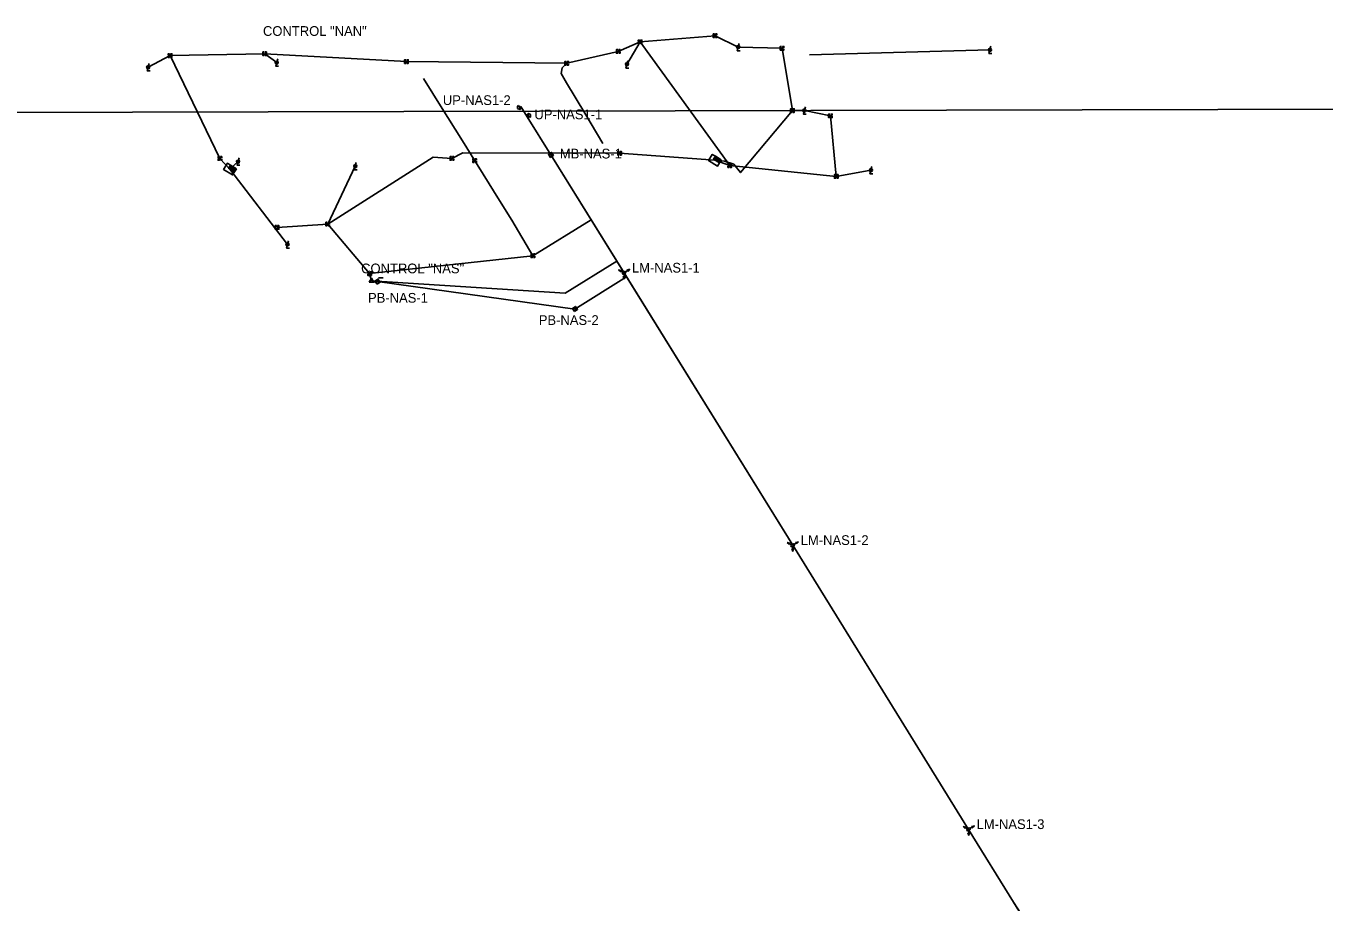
# Model space of a CAD drawing. Extents: x 1689971 to 1704302, y 703122 to 745602.
# Drawn here: x 1697142 to 1698211, y 718629 to 719350 of the extents above; entities that cross this region are included whole.
import ezdxf

# ---------------------------------------------------------------- set-up
doc = ezdxf.new("R2010")
doc.units = 0
for name, color, linetype in [('_CIVIL_CONSTRUCTION', 7, 'Continuous'), ('PF_X_Ground_Line', 7, 'Continuous'), ('RD_X_Cells', 7, 'Continuous'), ('RD_X_Concrete_Barrier', 7, 'Continuous'), ('SC_ProfileRun2', 7, 'Continuous'), ('SC_Scratch2', 7, 'Continuous'), ('SC_Scratch3', 7, 'Continuous'), ('SC_Scratch4', 7, 'Continuous'), ('SV_X_Control_Cells_Found', 7, 'Continuous'), ('SV_X_Mon_Cells_Found', 7, 'Continuous'), ('SV_X_Random_Point', 7, 'Continuous'), ('SV_X_Shot_Marker', 7, 'Continuous')]:
    doc.layers.add(name, color=color, linetype=linetype)

msp = doc.modelspace()

# ---------------------------------------------------------------- linework, layer by layer
at = {"layer": '_CIVIL_CONSTRUCTION'}
for p, q in [((1697630.1, 719329.4), (1697648.1, 719337.3)), ((1697648.1, 719337.3), (1697637.3, 719318.7)), ((1697709.9, 719342.3), (1697648.1, 719337.3)), ((1697722, 719235.4), (1697648.1, 719337.3)), ((1697709.9, 719342.3), (1697728.9, 719333)), ((1697243.1, 719316.4), (1697261.1, 719326)), ((1697261.1, 719326), (1697339, 719327.5)), ((1697302.1, 719241.3), (1697261.1, 719326)), ((1697455.7, 719321.1), (1697339, 719327.5)), ((1697339, 719327.5), (1697348.9, 719320.2)), ((1697630.1, 719329.4), (1697587.7, 719319.7)), ((1697765, 719332), (1697728.9, 719333)), ((1697773.6, 719280.7), (1697765, 719332)), ((1697936.2, 719330.6), (1697787.6, 719326.5)), ((1697587.7, 719319.7), (1697455.7, 719321.1)), ((1697773.6, 719280.7), (1697783.4, 719280.8)), ((1697773.6, 719280.7), (1697783.4, 719280.8)), ((1697783.4, 719280.8), (1697804.8, 719276.4)), ((1697809.6, 719226.5), (1697804.8, 719276.4)), ((1697302.1, 719241.3), (1697310.4, 719232.6)), ((1697317.1, 719238.7), (1697310.4, 719232.6)), ((1697631.3, 719245.6), (1697709.8, 719239.9)), ((1697709.8, 719239.9), (1697722, 719235.4)), ((1697310.4, 719232.6), (1697357.8, 719170.5)), ((1697390.9, 719187.3), (1697413.6, 719234.9)), ((1697809.6, 719226.5), (1697722, 719235.4)), ((1697809.6, 719226.5), (1697838.2, 719231.7)), ((1697349.2, 719184.5), (1697390.9, 719187.3)), ((1697559.9, 719161.2), (1697607.8, 719190.9)), ((1697559.9, 719161.2), (1697425.4, 719146.5))]:
    msp.add_line(p, q, dxfattribs=at)
for points in [[(1697587.6, 719303.5), (1697583.1, 719311.1), (1697584, 719315.9), (1697587.7, 719319.7)], [(1697500.6, 719257.9), (1697485.2, 719282.5), (1697469.8, 719307.1)], [(1697617.4, 719253.7), (1697602.5, 719278.6), (1697587.6, 719303.5)], [(1697709.8, 719239.9), (1697717.5, 719239.2), (1697725.3, 719236.5), (1697730.9, 719229.7), (1697773.6, 719280.7)], [(1697559.9, 719161.2), (1697542.4, 719190.6), (1697532.4, 719206.7), (1697500.6, 719257.9)], [(1697390.9, 719187.3), (1697477.7, 719242.5), (1697493.2, 719241.4)], [(1697493.2, 719241.4), (1697502.2, 719245.9), (1697631.3, 719245.6)], [(1697426.9, 719140.6), (1697425.4, 719146.5), (1697390.9, 719187.3)]]:
    msp.add_lwpolyline(points, dxfattribs=at)
at = {"layer": 'PF_X_Ground_Line'}
msp.add_lwpolyline([(1697425, 719139.4), (1697428.9, 719139.4), (1697426.9, 719142.9)], close=True, dxfattribs=at)
at = {"layer": 'RD_X_Cells'}
for p, q in [((1697634.9, 719147.2), (1697574.7, 719244.3)), ((1697637, 719143.8), (1697594.5, 719117.4)), ((1697773.8, 718922.9), (1697634.9, 719147.2)), ((1697426.9, 719140.6), (1697431.9, 719140)), ((1697918.6, 718689.1), (1697773.8, 718922.9)), ((1697955.6, 718629.3), (1697918.6, 718689.1))]:
    msp.add_line(p, q, dxfattribs=at)
msp.add_arc((1700391, 720137.9), 2864.8, 211.776, 215.5389, dxfattribs=at)
at = {"layer": 'RD_X_Concrete_Barrier'}
for p, q in [((1697550, 719284.2), (1697548.3, 719283.2)), ((1697555.2, 719275.7), (1697550, 719284.2)), ((1697555.2, 719275.7), (1697556.9, 719276.8)), ((1697574.7, 719244.3), (1697555.2, 719275.7)), ((1697629, 719156.7), (1697574.7, 719244.3)), ((1697773.8, 718922.9), (1697629, 719156.7)), ((1697431.9, 719140), (1697594.5, 719117.4)), ((1697918.6, 718689.1), (1697773.8, 718922.9)), ((1697955.6, 718629.3), (1697918.6, 718689.1))]:
    msp.add_line(p, q, dxfattribs=at)
msp.add_arc((1700391, 720137.9), 2864.8, 211.776, 215.3689, dxfattribs=at)
at = {"layer": 'SC_ProfileRun2'}
for p, q in [((1697711.8, 719241.8), (1697708.9, 719240.7)), ((1697710.1, 719242.8), (1697710.5, 719239.7)), ((1697714.8, 719240.1), (1697710.4, 719239.6)), ((1697711.8, 719241.9), (1697713.4, 719237.8)), ((1697312.4, 719234.5), (1697309.6, 719233.5)), ((1697310.8, 719235.5), (1697311.2, 719232.5)), ((1697315.5, 719232.8), (1697311.1, 719232.4)), ((1697312.5, 719234.6), (1697314.1, 719230.5))]:
    msp.add_line(p, q, dxfattribs=at)
for points in [[(1697315.7, 719232.9), (1697314.2, 719230.3), (1697312.6, 719227.7), (1697305.1, 719232.3), (1697308.3, 719237.4), (1697310.8, 719235.9)], [(1697715, 719240.2), (1697713.5, 719237.6), (1697711.9, 719235), (1697704.5, 719239.6), (1697707.6, 719244.7), (1697710.1, 719243.1)], [(1697708.9, 719240.7), (1697710.1, 719242.8), (1697711.8, 719241.8), (1697710.5, 719239.7)], [(1697713.4, 719237.8), (1697710.4, 719239.6), (1697711.8, 719241.9), (1697714.8, 719240.1)], [(1697309.6, 719233.5), (1697310.8, 719235.5), (1697312.4, 719234.5), (1697311.2, 719232.5)], [(1697314.1, 719230.5), (1697311.1, 719232.4), (1697312.5, 719234.6), (1697315.5, 719232.8)]]:
    msp.add_lwpolyline(points, close=True, dxfattribs=at)
for points in [[(1697710.1, 719243.1), (1697708.6, 719240.6), (1697713.5, 719237.6)], [(1697310.8, 719235.9), (1697309.3, 719233.3), (1697314.2, 719230.3)]]:
    msp.add_lwpolyline(points, dxfattribs=at)
at = {"layer": 'SC_Scratch2'}
for p in [(1697548.3, 719283.2), (1697555.2, 719275.7)]:
    msp.add_line(p, (1697550, 719284.2), dxfattribs=at)
at = {"layer": 'SC_Scratch3'}
for points in [[(1697729.7, 719336), (1697728.2, 719330), (1697730.5, 719330)], [(1697937, 719333.6), (1697935.4, 719327.6), (1697937.8, 719327.6)], [(1697349.7, 719323.2), (1697348.1, 719317.2), (1697350.5, 719317.2)], [(1697243.9, 719319.4), (1697242.3, 719313.4), (1697244.7, 719313.4)], [(1697638.1, 719321.7), (1697636.5, 719315.7), (1697638.9, 719315.7)], [(1697784.2, 719283.8), (1697782.6, 719277.8), (1697785, 719277.8)], [(1697317.9, 719241.7), (1697316.3, 719235.7), (1697318.6, 719235.7)], [(1697414.4, 719237.9), (1697412.8, 719231.9), (1697415.2, 719231.9)], [(1697839, 719234.7), (1697837.4, 719228.7), (1697839.8, 719228.7)], [(1697358.6, 719173.5), (1697357, 719167.6), (1697359.4, 719167.6)]]:
    msp.add_lwpolyline(points, dxfattribs=at)
for centre in [(1697728.9, 719333.1), (1697936.2, 719330.7), (1697243.1, 719316.4), (1697348.9, 719320.2), (1697637.3, 719318.8), (1697783.4, 719280.8), (1697317.1, 719238.7), (1697413.6, 719235), (1697838.2, 719231.7), (1697357.8, 719170.6)]:
    msp.add_circle(centre, 1.3, dxfattribs=at)
at = {"layer": 'SC_Scratch4'}
for p, q in [((1697648.1, 719337.3), (1697648.1, 719337.3)), ((1697709.9, 719342.3), (1697709.9, 719342.3)), ((1697261.1, 719326), (1697261.1, 719326)), ((1697339, 719327.5), (1697339, 719327.5)), ((1697630.1, 719329.4), (1697630.1, 719329.4)), ((1697765, 719332), (1697765, 719332)), ((1697455.7, 719321.1), (1697455.7, 719321.1)), ((1697587.7, 719319.7), (1697587.7, 719319.7)), ((1697773.6, 719280.7), (1697773.6, 719280.7)), ((1697804.8, 719276.4), (1697804.8, 719276.4)), ((1697302.1, 719241.3), (1697302.1, 719241.3)), ((1697493.2, 719241.4), (1697493.2, 719241.4)), ((1697511.9, 719239.6), (1697511.9, 719239.6)), ((1697631.3, 719245.6), (1697631.3, 719245.6)), ((1697722, 719235.4), (1697722, 719235.4)), ((1697809.6, 719226.5), (1697809.6, 719226.5)), ((1697349.2, 719184.5), (1697349.2, 719184.5)), ((1697390.9, 719187.3), (1697390.9, 719187.3)), ((1697559.9, 719161.2), (1697559.9, 719161.2)), ((1697425.4, 719146.5), (1697425.4, 719146.5))]:
    msp.add_line(p, q, dxfattribs=at)
for points in [[(1697647.7, 719338.8), (1697646.6, 719338.8), (1697646.6, 719337.7)], [(1697646.6, 719336.9), (1697646.6, 719335.8), (1697647.7, 719335.8)], [(1697647, 719338.3), (1697647, 719336.3), (1697648.1, 719336.3)], [(1697648, 719338.3), (1697649.3, 719338.3)], [(1697649.6, 719337.7), (1697649.6, 719338.8), (1697648.5, 719338.8)], [(1697648.5, 719335.8), (1697649.6, 719335.8), (1697649.6, 719336.9)], [(1697648.7, 719338.3), (1697648.7, 719336.3)], [(1697709.5, 719343.8), (1697708.4, 719343.8), (1697708.4, 719342.7)], [(1697708.4, 719341.9), (1697708.4, 719340.8), (1697709.5, 719340.8)], [(1697708.8, 719343.3), (1697708.8, 719341.3), (1697709.9, 719341.3)], [(1697709.8, 719343.3), (1697711.1, 719343.3)], [(1697711.4, 719342.7), (1697711.4, 719343.8), (1697710.3, 719343.8)], [(1697710.3, 719340.8), (1697711.4, 719340.8), (1697711.4, 719341.9)], [(1697710.5, 719343.3), (1697710.5, 719341.3)], [(1697260.7, 719327.5), (1697259.6, 719327.5), (1697259.6, 719326.4)], [(1697259.6, 719325.6), (1697259.6, 719324.5), (1697260.7, 719324.5)], [(1697260, 719327), (1697260, 719325), (1697261.1, 719325)], [(1697261, 719327), (1697262.3, 719327)], [(1697262.6, 719326.4), (1697262.6, 719327.5), (1697261.5, 719327.5)], [(1697261.5, 719324.5), (1697262.6, 719324.5), (1697262.6, 719325.6)], [(1697261.6, 719327), (1697261.6, 719325)], [(1697338.6, 719329), (1697337.5, 719329), (1697337.5, 719327.9)], [(1697337.5, 719327.1), (1697337.5, 719326), (1697338.6, 719326)], [(1697337.9, 719328.5), (1697337.9, 719326.5), (1697339, 719326.5)], [(1697339, 719328.5), (1697340.2, 719328.5)], [(1697340.5, 719327.9), (1697340.5, 719329), (1697339.4, 719329)], [(1697339.4, 719326), (1697340.5, 719326), (1697340.5, 719327.1)], [(1697339.6, 719328.5), (1697339.6, 719326.5)], [(1697629.7, 719330.9), (1697628.6, 719330.9), (1697628.6, 719329.8)], [(1697628.6, 719329), (1697628.6, 719327.9), (1697629.7, 719327.9)], [(1697629, 719330.4), (1697629, 719328.4), (1697630.1, 719328.4)], [(1697630, 719330.4), (1697631.3, 719330.4)], [(1697631.6, 719329.8), (1697631.6, 719330.9), (1697630.5, 719330.9)], [(1697630.5, 719327.9), (1697631.6, 719327.9), (1697631.6, 719329)], [(1697630.6, 719330.4), (1697630.6, 719328.4)], [(1697764.6, 719333.5), (1697763.5, 719333.5), (1697763.5, 719332.4)], [(1697763.5, 719331.6), (1697763.5, 719330.5), (1697764.6, 719330.5)], [(1697764, 719333), (1697764, 719331), (1697765, 719331)], [(1697765, 719333), (1697766.2, 719333)], [(1697766.5, 719332.4), (1697766.5, 719333.5), (1697765.4, 719333.5)], [(1697765.4, 719330.5), (1697766.5, 719330.5), (1697766.5, 719331.6)], [(1697765.6, 719333), (1697765.6, 719331)], [(1697455.3, 719322.6), (1697454.2, 719322.6), (1697454.2, 719321.5)], [(1697454.2, 719320.7), (1697454.2, 719319.6), (1697455.3, 719319.6)], [(1697454.7, 719322.1), (1697454.7, 719320.1), (1697455.7, 719320.1)], [(1697455.7, 719322.1), (1697456.9, 719322.1)], [(1697457.2, 719321.5), (1697457.2, 719322.6), (1697456.1, 719322.6)], [(1697456.1, 719319.6), (1697457.2, 719319.6), (1697457.2, 719320.7)], [(1697456.3, 719322.1), (1697456.3, 719320.1)], [(1697587.3, 719321.2), (1697586.2, 719321.2), (1697586.2, 719320.1)], [(1697586.2, 719319.3), (1697586.2, 719318.2), (1697587.3, 719318.2)], [(1697586.6, 719320.7), (1697586.6, 719318.7), (1697587.7, 719318.7)], [(1697587.6, 719320.7), (1697588.9, 719320.7)], [(1697589.2, 719320.1), (1697589.2, 719321.2), (1697588.1, 719321.2)], [(1697588.1, 719318.2), (1697589.2, 719318.2), (1697589.2, 719319.3)], [(1697588.3, 719320.7), (1697588.3, 719318.7)], [(1697773.2, 719282.2), (1697772.1, 719282.2), (1697772.1, 719281.1)], [(1697772.1, 719280.3), (1697772.1, 719279.2), (1697773.2, 719279.2)], [(1697772.5, 719281.7), (1697772.5, 719279.7), (1697773.6, 719279.7)], [(1697773.6, 719281.7), (1697774.8, 719281.7)], [(1697775.1, 719281.1), (1697775.1, 719282.2), (1697774, 719282.2)], [(1697774, 719279.2), (1697775.1, 719279.2), (1697775.1, 719280.3)], [(1697774.2, 719281.7), (1697774.2, 719279.7)], [(1697804.4, 719277.9), (1697803.3, 719277.9), (1697803.3, 719276.8)], [(1697803.3, 719276), (1697803.3, 719274.9), (1697804.4, 719274.9)], [(1697803.7, 719277.4), (1697803.7, 719275.4), (1697804.8, 719275.4)], [(1697804.8, 719277.4), (1697806, 719277.4)], [(1697806.3, 719276.8), (1697806.3, 719277.9), (1697805.2, 719277.9)], [(1697805.2, 719274.9), (1697806.3, 719274.9), (1697806.3, 719276)], [(1697805.4, 719277.4), (1697805.4, 719275.4)], [(1697301.7, 719242.8), (1697300.6, 719242.8), (1697300.6, 719241.7)], [(1697300.6, 719240.9), (1697300.6, 719239.8), (1697301.7, 719239.8)], [(1697301.1, 719242.3), (1697301.1, 719240.3), (1697302.1, 719240.3)], [(1697302.1, 719242.3), (1697303.3, 719242.3)], [(1697303.6, 719241.7), (1697303.6, 719242.8), (1697302.5, 719242.8)], [(1697302.5, 719239.8), (1697303.6, 719239.8), (1697303.6, 719240.9)], [(1697302.7, 719242.3), (1697302.7, 719240.3)], [(1697492.8, 719242.9), (1697491.7, 719242.9), (1697491.7, 719241.8)], [(1697491.7, 719241), (1697491.7, 719239.9), (1697492.8, 719239.9)], [(1697492.1, 719242.4), (1697492.1, 719240.4), (1697493.2, 719240.4)], [(1697493.1, 719242.4), (1697494.4, 719242.4)], [(1697494.7, 719241.8), (1697494.7, 719242.9), (1697493.6, 719242.9)], [(1697493.6, 719239.9), (1697494.7, 719239.9), (1697494.7, 719241)], [(1697493.8, 719242.4), (1697493.8, 719240.4)], [(1697511.5, 719241.1), (1697510.4, 719241.1), (1697510.4, 719240)], [(1697510.4, 719239.2), (1697510.4, 719238.1), (1697511.5, 719238.1)], [(1697510.8, 719240.6), (1697510.8, 719238.6), (1697511.9, 719238.6)], [(1697511.9, 719240.6), (1697513.1, 719240.6)], [(1697513.4, 719240), (1697513.4, 719241.1), (1697512.3, 719241.1)], [(1697512.3, 719238.1), (1697513.4, 719238.1), (1697513.4, 719239.2)], [(1697512.5, 719240.6), (1697512.5, 719238.6)], [(1697630.9, 719247.1), (1697629.8, 719247.1), (1697629.8, 719246)], [(1697629.8, 719245.2), (1697629.8, 719244.1), (1697630.9, 719244.1)], [(1697630.2, 719246.6), (1697630.2, 719244.6), (1697631.3, 719244.6)], [(1697631.3, 719246.6), (1697632.5, 719246.6)], [(1697632.8, 719246), (1697632.8, 719247.1), (1697631.7, 719247.1)], [(1697631.7, 719244.1), (1697632.8, 719244.1), (1697632.8, 719245.2)], [(1697631.9, 719246.6), (1697631.9, 719244.6)], [(1697721.6, 719236.9), (1697720.5, 719236.9), (1697720.5, 719235.8)], [(1697720.5, 719235), (1697720.5, 719233.9), (1697721.6, 719233.9)], [(1697720.9, 719236.4), (1697720.9, 719234.4), (1697722, 719234.4)], [(1697722, 719236.4), (1697723.2, 719236.4)], [(1697723.5, 719235.8), (1697723.5, 719236.9), (1697722.4, 719236.9)], [(1697722.4, 719233.9), (1697723.5, 719233.9), (1697723.5, 719235)], [(1697722.6, 719236.4), (1697722.6, 719234.4)], [(1697809.2, 719228), (1697808.1, 719228), (1697808.1, 719226.9)], [(1697808.5, 719227.5), (1697808.5, 719225.5), (1697809.6, 719225.5)], [(1697809.5, 719227.5), (1697810.8, 719227.5)], [(1697811.1, 719226.9), (1697811.1, 719228), (1697810, 719228)], [(1697810.1, 719227.5), (1697810.1, 719225.5)], [(1697808.1, 719226.1), (1697808.1, 719225), (1697809.2, 719225)], [(1697810, 719225), (1697811.1, 719225), (1697811.1, 719226.1)], [(1697348.8, 719186), (1697347.7, 719186), (1697347.7, 719184.9)], [(1697347.7, 719184.1), (1697347.7, 719183), (1697348.8, 719183)], [(1697348.1, 719185.5), (1697348.1, 719183.5), (1697349.2, 719183.5)], [(1697349.1, 719185.5), (1697350.4, 719185.5)], [(1697350.7, 719184.9), (1697350.7, 719186), (1697349.6, 719186)], [(1697349.6, 719183), (1697350.7, 719183), (1697350.7, 719184.1)], [(1697349.8, 719185.5), (1697349.8, 719183.5)], [(1697390.5, 719188.8), (1697389.4, 719188.8), (1697389.4, 719187.7)], [(1697389.4, 719186.9), (1697389.4, 719185.8), (1697390.5, 719185.8)], [(1697389.8, 719188.3), (1697389.8, 719186.3), (1697390.9, 719186.3)], [(1697390.9, 719188.3), (1697392.1, 719188.3)], [(1697392.4, 719187.7), (1697392.4, 719188.8), (1697391.3, 719188.8)], [(1697391.3, 719185.8), (1697392.4, 719185.8), (1697392.4, 719186.9)], [(1697391.5, 719188.3), (1697391.5, 719186.3)], [(1697559.5, 719162.7), (1697558.4, 719162.7), (1697558.4, 719161.6)], [(1697561.4, 719161.6), (1697561.4, 719162.7), (1697560.3, 719162.7)], [(1697558.4, 719160.8), (1697558.4, 719159.7), (1697559.5, 719159.7)], [(1697558.8, 719162.2), (1697558.8, 719160.2), (1697559.9, 719160.2)], [(1697559.8, 719162.2), (1697561.1, 719162.2)], [(1697560.3, 719159.7), (1697561.4, 719159.7), (1697561.4, 719160.8)], [(1697560.5, 719162.2), (1697560.5, 719160.2)], [(1697425, 719148), (1697423.9, 719148), (1697423.9, 719146.9)], [(1697423.9, 719146.1), (1697423.9, 719145), (1697425, 719145)], [(1697424.3, 719147.5), (1697424.3, 719145.5), (1697425.4, 719145.5)], [(1697425.4, 719147.5), (1697426.6, 719147.5)], [(1697426.9, 719146.9), (1697426.9, 719148), (1697425.8, 719148)], [(1697425.8, 719145), (1697426.9, 719145), (1697426.9, 719146.1)], [(1697426, 719147.5), (1697426, 719145.5)]]:
    msp.add_lwpolyline(points, dxfattribs=at)
at = {"layer": 'SV_X_Control_Cells_Found'}
for p, q in [((1697632.8, 719149), (1697630.4, 719149.6)), ((1697630.4, 719149.6), (1697632.2, 719147.9)), ((1697633.9, 719147.7), (1697632.3, 719148.5)), ((1697634.3, 719144.5), (1697635, 719142.1)), ((1697634.9, 719146.1), (1697635, 719144.3)), ((1697635, 719142.1), (1697635.6, 719144.5)), ((1697636.2, 719148), (1697637.8, 719149)), ((1697639.6, 719150.1), (1697637.3, 719149.4)), ((1697637.9, 719148.3), (1697639.6, 719150.1)), ((1697771.7, 718924.8), (1697769.3, 718925.3)), ((1697769.3, 718925.3), (1697771.1, 718923.6)), ((1697772.8, 718923.4), (1697771.2, 718924.3)), ((1697773.2, 718920.2), (1697773.9, 718917.8)), ((1697773.8, 718921.8), (1697773.9, 718920)), ((1697773.9, 718917.8), (1697774.5, 718920.2)), ((1697775.1, 718923.8), (1697776.7, 718924.7)), ((1697778.6, 718925.9), (1697776.2, 718925.1)), ((1697776.8, 718924), (1697778.6, 718925.9)), ((1697916.5, 718691), (1697914.1, 718691.6)), ((1697914.1, 718691.6), (1697915.9, 718689.9)), ((1697917.6, 718689.7), (1697916.1, 718690.5)), ((1697918, 718686.4), (1697918.7, 718684.1)), ((1697918.6, 718688), (1697918.7, 718686.3)), ((1697918.7, 718684.1), (1697919.3, 718686.5)), ((1697920, 718690), (1697921.5, 718690.9)), ((1697923.4, 718692.1), (1697921, 718691.4)), ((1697921.7, 718690.3), (1697923.4, 718692.1))]:
    msp.add_line(p, q, dxfattribs=at)
for points in [[(1697548, 719284.9), (1697549.8, 719282.2), (1697549, 719281.7), (1697547.3, 719282.5), (1697547.2, 719284.4)], [(1697557.2, 719275), (1697555.4, 719277.7), (1697556.2, 719278.2), (1697557.9, 719277.4), (1697558, 719275.5)]]:
    msp.add_lwpolyline(points, close=True, dxfattribs=at)
for centre, start, end in [((1697633.3, 719148), 117.237, 186.3149), ((1697634.9, 719145.4), 237.237, 306.3149), ((1697636.8, 719148.4), 357.237, 66.3149), ((1697772.2, 718923.8), 117.0577, 186.1355), ((1697773.8, 718921.2), 237.0577, 306.1355), ((1697775.7, 718924.1), 357.0577, 66.1355), ((1697917.1, 718690), 116.9143, 185.9922), ((1697918.6, 718687.4), 236.9143, 305.9922), ((1697920.5, 718690.3), 356.9143, 65.9922)]:
    msp.add_arc(centre, 1.13, start, end, dxfattribs=at)
for centre, major_axis in [((1697634.9, 719147.2), (1.36, 0.84)), ((1697773.8, 718922.9), (1.36, 0.84)), ((1697918.6, 718689.1), (1.36, 0.83))]:
    msp.add_ellipse(centre, major_axis=major_axis, ratio=0.625, dxfattribs=at)
at = {"layer": 'SV_X_Mon_Cells_Found'}
msp.add_line((1697555.2, 719275.7), (1697556.9, 719276.8), dxfattribs=at)
at = {"layer": 'SV_X_Random_Point'}
for p, q in [((1698867.3, 719283.4), (1696073.6, 719276.6)), ((1697629, 719156.7), (1697586.5, 719130.4)), ((1697432.6, 719143.1), (1697436.6, 719143.1)), ((1697426.9, 719140.6), (1697586.5, 719130.4)), ((1697431.9, 719140), (1697426.9, 719140.6))]:
    msp.add_line(p, q, dxfattribs=at)
at = {"layer": 'SV_X_Shot_Marker'}
for p, q in [((1697574.7, 719244.3), (1697574.7, 719244.3)), ((1697431.9, 719140), (1697431.9, 719140)), ((1697594.5, 719117.4), (1697594.5, 719117.4))]:
    msp.add_line(p, q, dxfattribs=at)
for points in [[(1697574.2, 719242.2), (1697572.7, 719244.8), (1697575.2, 719246.3), (1697576.8, 719243.8)], [(1697431.5, 719137.9), (1697429.8, 719140.4), (1697432.3, 719142.1), (1697434, 719139.6)], [(1697594.1, 719115.4), (1697592.4, 719117.8), (1697594.9, 719119.5), (1697596.6, 719117)]]:
    msp.add_lwpolyline(points, close=True, dxfattribs=at)
for points in [[(1697573.9, 719243.7), (1697573.2, 719244.8)], [(1697573.6, 719244.2), (1697575.3, 719245.3)], [(1697574.4, 719242.8), (1697576.1, 719243.9), (1697575.6, 719244.8)], [(1697431.1, 719139.4), (1697430.4, 719140.4)], [(1697430.7, 719139.9), (1697432.4, 719141)], [(1697431.7, 719138.5), (1697433.3, 719139.6), (1697432.7, 719140.5)], [(1697593.7, 719116.8), (1697593, 719117.9)], [(1697593.3, 719117.4), (1697595, 719118.5)], [(1697594.3, 719116), (1697595.9, 719117.1), (1697595.3, 719118)]]:
    msp.add_lwpolyline(points, dxfattribs=at)

# ---------------------------------------------------------------- texts
at = {"layer": 'SV_X_Random_Point'}
for s, p in [('CONTROL "NAN"', (1697337.6, 719342.2)), ('UP-NAS1-2', (1697485.7, 719285.3)), ('UP-NAS1-1', (1697561.1, 719273.6)), ('MB-NAS-1', (1697582, 719241.3)), ('CONTROL "NAS"', (1697418.4, 719146.8)), ('LM-NAS1-1', (1697641.4, 719147.4)), ('PB-NAS-1', (1697424.1, 719122.6)), ('PB-NAS-2', (1697564.7, 719104.3)), ('LM-NAS1-2', (1697780.4, 718923.2)), ('LM-NAS1-3', (1697925.2, 718689.4))]:
    msp.add_text(s, height=8, dxfattribs=at).set_placement(p)

doc.saveas('drawing.dxf')
